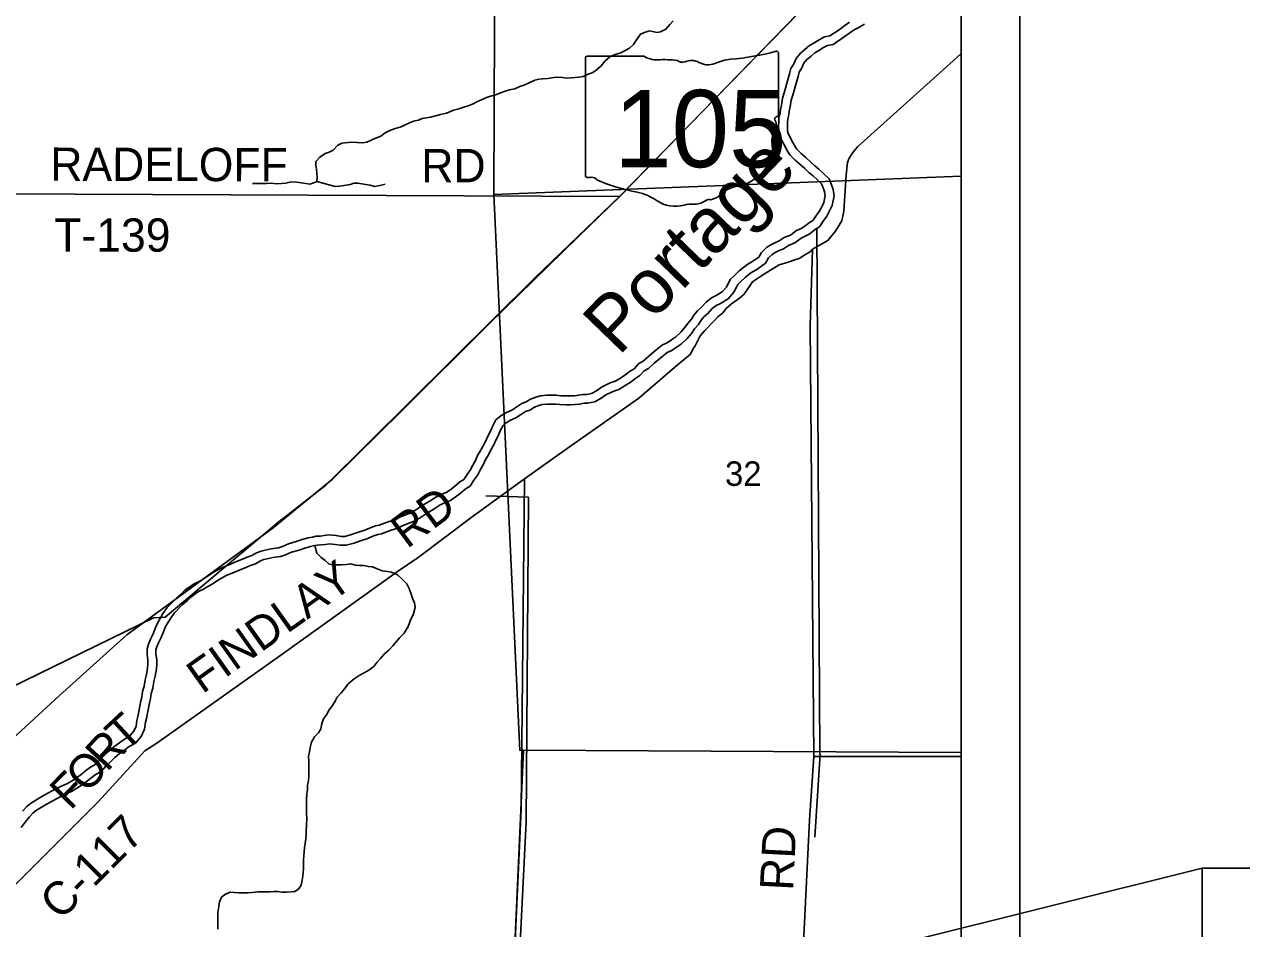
# Model space of a CAD drawing. Extents: x 0 to 34, y 0 to 22.
# Drawn here: x 7.301 to 9.379, y 18.196 to 19.739 of the extents above; entities that cross this region are included whole.
import ezdxf

# ---------------------------------------------------------------- set-up
doc = ezdxf.new("R2010")
doc.units = 0
for name, color, linetype in [('Default', 7, 'Continuous'), ('GM_X_County_Road', 7, 'Continuous'), ('GM_X_County_Road_Text', 7, 'Continuous'), ('GM_X_Major_River', 7, 'Continuous'), ('GM_X_Major_River_Text', 7, 'Continuous'), ('GM_X_Minor_River', 7, 'Continuous'), ('GM_X_Rail_Line', 7, 'Continuous'), ('GM_X_Section_Text', 7, 'Continuous'), ('GM_X_State_Location', 7, 'Continuous'), ('GM_X_State_Route', 7, 'Continuous'), ('GM_X_State_Shield', 7, 'Continuous'), ('GM_X_Township_Road', 7, 'Continuous'), ('GM_X_Township_Road_Text', 7, 'Continuous'), ('SH_Cut_Line', 7, 'Continuous'), ('SH_Data', 7, 'Continuous'), ('SH_Text', 7, 'Continuous')]:
    doc.layers.add(name, color=color, linetype=linetype)

msp = doc.modelspace()

# ---------------------------------------------------------------- linework, layer by layer
at = {"layer": 'Default'}
msp.add_lwpolyline([(8.9, 16.9874), (8.9, 20.9)], dxfattribs=at)
for points in [[(8.9, 19.4792), (8.9, 20.4788), (8.1063, 20.4559), (8.1023, 19.4482)], [(8.9, 18.4963), (8.9, 19.4792), (8.1023, 19.4482), (8.1467, 18.4995), (8.1531, 18.4998)], [(8.9, 17.4952), (8.9, 18.4963), (8.1531, 18.4998), (8.1087, 17.5031)]]:
    msp.add_lwpolyline(points, close=True, dxfattribs=at)
at = {"layer": 'GM_X_County_Road'}
msp.add_lwpolyline([(7.2847, 18.2696), (7.4268, 18.4117), (7.5065, 18.4991), (7.527, 18.5121), (7.7389, 18.6622), (7.9397, 18.8059), (7.9731, 18.8287), (8.065, 18.8983), (8.1546, 18.9633), (8.2275, 19.0149), (8.3497, 19.1008), (8.4112, 19.1537), (8.4378, 19.1757), (8.442, 19.1841), (8.4458, 19.1901), (8.4504, 19.1993), (8.4545, 19.2069), (8.4621, 19.2164), (8.4777, 19.2319), (8.4845, 19.2395), (8.4929, 19.246), (8.4986, 19.2536), (8.5077, 19.2616), (8.5218, 19.2715), (8.5297, 19.2779), (8.5438, 19.2992), (8.5624, 19.3118), (8.5893, 19.3281), (8.6045, 19.3327), (8.6159, 19.3368), (8.6231, 19.3391), (8.633, 19.3452), (8.6421, 19.3502), (8.6463, 19.3547), (8.6725, 19.3695), (8.6854, 19.3855), (8.696, 19.403), (8.6995, 19.4197), (8.7037, 19.482), (8.706, 19.5029), (8.7086, 19.5101), (8.7151, 19.5196), (8.7174, 19.5226), (8.7231, 19.5295), (8.8864, 19.6764), (8.9, 19.6888)], dxfattribs=at)
at = {"layer": 'GM_X_Major_River'}
for points in [[(8.7092, 19.742), (8.7013, 19.7366), (8.6915, 19.7294), (8.6756, 19.7187), (8.6665, 19.7171), (8.6574, 19.7121), (8.6475, 19.706), (8.6411, 19.7022), (8.6339, 19.696), (8.6256, 19.6892), (8.6184, 19.6804), (8.6143, 19.6713), (8.6094, 19.6633), (8.6067, 19.6538), (8.6026, 19.6382), (8.6, 19.6298), (8.5978, 19.6215), (8.5951, 19.6123), (8.5933, 19.6006), (8.5914, 19.5933), (8.5907, 19.5869), (8.5888, 19.5793), (8.5885, 19.5721), (8.5881, 19.5656), (8.5885, 19.5569), (8.5893, 19.5497), (8.597, 19.5338), (8.6035, 19.522)], [(8.6169, 19.5292), (8.6104, 19.5407), (8.6041, 19.5539), (8.6036, 19.5581), (8.6033, 19.5655), (8.6036, 19.5713), (8.6039, 19.5771), (8.6056, 19.5842), (8.6064, 19.5906), (8.6082, 19.5975), (8.61, 19.609), (8.6124, 19.6174), (8.6146, 19.6256), (8.6172, 19.634), (8.6214, 19.6498), (8.6234, 19.6572), (8.6277, 19.6641), (8.6314, 19.6723), (8.6364, 19.6784), (8.6436, 19.6844), (8.6499, 19.6898), (8.6554, 19.693), (8.665, 19.699), (8.6715, 19.7026), (8.6813, 19.7043), (8.7002, 19.717), (8.71, 19.7242), (8.7171, 19.729), (8.7231, 19.7322), (8.7349, 19.7391)], [(8.6035, 19.522), (8.6077, 19.5156), (8.6168, 19.5069), (8.6248, 19.5001), (8.6328, 19.4926), (8.6404, 19.4854), (8.6473, 19.4801), (8.6553, 19.4726), (8.6617, 19.4665), (8.6644, 19.4593), (8.6667, 19.4529), (8.6679, 19.4465), (8.6653, 19.4343), (8.6619, 19.4274), (8.6577, 19.4194), (8.6517, 19.4114), (8.6472, 19.4042), (8.6407, 19.4), (8.6332, 19.3939), (8.6267, 19.3904), (8.6188, 19.3866), (8.6086, 19.379), (8.5979, 19.3747), (8.5892, 19.369), (8.5817, 19.3655), (8.5752, 19.3625), (8.5677, 19.3575), (8.559, 19.3495), (8.5544, 19.3415), (8.5427, 19.3331), (8.5359, 19.3292), (8.5287, 19.3243), (8.5211, 19.3181), (8.5128, 19.3101), (8.5064, 19.304), (8.503, 19.2972), (8.4992, 19.2903), (8.492, 19.2819), (8.4818, 19.2758), (8.4739, 19.272), (8.4644, 19.2647), (8.4569, 19.2559), (8.4497, 19.2498), (8.4436, 19.2422), (8.4395, 19.2353), (8.4331, 19.2281), (8.4278, 19.2205), (8.4214, 19.2132), (8.4123, 19.2048), (8.4055, 19.2002), (8.3983, 19.1953), (8.3903, 19.1914), (8.3816, 19.1849), (8.3752, 19.1796), (8.3661, 19.1719), (8.3574, 19.1639), (8.3495, 19.1597), (8.3415, 19.1509), (8.334, 19.146), (8.3275, 19.141), (8.3165, 19.1337), (8.3094, 19.1295), (8.301, 19.1268), (8.2942, 19.1234), (8.2859, 19.1195), (8.2775, 19.1134), (8.2692, 19.1088), (8.2609, 19.1072), (8.2544, 19.1072), (8.2468, 19.1056), (8.24, 19.1049), (8.2324, 19.1044), (8.226, 19.1044), (8.2165, 19.1047), (8.2089, 19.1058), (8.1926, 19.1057), (8.182, 19.1049), (8.1755, 19.103), (8.1649, 19.0988), (8.1573, 19.0942), (8.1498, 19.0915), (8.1414, 19.0861), (8.1327, 19.0804), (8.124, 19.0765), (8.1145, 19.0712), (8.1058, 19.0635), (8.0998, 19.0525), (8.0961, 19.043), (8.0912, 19.0346), (8.0885, 19.0278), (8.0832, 19.0182), (8.0791, 19.0102), (8.0746, 19.003), (8.0712, 18.9946), (8.0663, 18.9863), (8.0618, 18.9779), (8.0554, 18.9687), (8.0512, 18.9619), (8.0444, 18.9581), (8.0349, 18.9497), (8.0274, 18.9439)], [(8.0365, 18.9318), (8.0446, 18.9379), (8.0532, 18.9456), (8.0621, 18.9506), (8.0681, 18.9605), (8.0747, 18.9699), (8.0795, 18.9788), (8.0848, 18.9879), (8.0881, 18.9961), (8.0923, 19.0027), (8.0966, 19.0111), (8.1023, 19.0213), (8.1049, 19.028), (8.1097, 19.0363), (8.1136, 19.046), (8.1179, 19.0539), (8.1234, 19.0587), (8.1308, 19.063), (8.14, 19.067), (8.1497, 19.0734), (8.1565, 19.0778), (8.1639, 19.0804), (8.1717, 19.0851), (8.1805, 19.0887), (8.1847, 19.0899), (8.1932, 19.0906), (8.2078, 19.0907), (8.2151, 19.0896), (8.2257, 19.0892), (8.2329, 19.0893), (8.2413, 19.0897), (8.2492, 19.0907), (8.256, 19.0921), (8.2623, 19.0921), (8.2744, 19.0944), (8.2857, 19.1006), (8.2936, 19.1064), (8.3008, 19.1097), (8.3068, 19.1128), (8.3156, 19.1156), (8.3246, 19.1209), (8.3364, 19.1287), (8.3428, 19.1336), (8.3515, 19.1393), (8.3589, 19.1476), (8.3662, 19.1515), (8.3761, 19.1606), (8.3849, 19.168), (8.391, 19.173), (8.3982, 19.1784), (8.4059, 19.1821), (8.414, 19.1877), (8.4217, 19.1929), (8.4322, 19.2026), (8.4397, 19.2111), (8.445, 19.2187), (8.4517, 19.2263), (8.4561, 19.2335), (8.4606, 19.2392), (8.4676, 19.2451), (8.4749, 19.2536), (8.4819, 19.259), (8.489, 19.2624), (8.502, 19.2702), (8.5118, 19.2816), (8.5164, 19.2902), (8.5188, 19.2949), (8.5233, 19.2992), (8.5312, 19.3068), (8.5378, 19.3121), (8.5439, 19.3164), (8.5509, 19.3203), (8.566, 19.3311), (8.571, 19.3399), (8.577, 19.3455), (8.5827, 19.3492), (8.5881, 19.3518), (8.5966, 19.3557), (8.605, 19.3612), (8.616, 19.3656), (8.6267, 19.3736), (8.6336, 19.3769), (8.6416, 19.3812), (8.6497, 19.3877), (8.6582, 19.3933), (8.6642, 19.4028), (8.6706, 19.4113), (8.6754, 19.4206), (8.6797, 19.4293), (8.6833, 19.4462), (8.6814, 19.4568), (8.6786, 19.4645), (8.6747, 19.4752), (8.6656, 19.4836), (8.6571, 19.4917), (8.6502, 19.497), (8.6432, 19.5036), (8.6349, 19.5114), (8.6269, 19.5182), (8.6194, 19.5254), (8.6169, 19.5292)], [(7.2953, 18.3682), (7.3026, 18.3772), (7.3095, 18.3863), (7.3155, 18.3927), (7.3202, 18.3967), (7.3284, 18.4015), (7.3371, 18.4068), (7.3472, 18.4127), (7.3579, 18.4183), (7.3671, 18.4231), (7.3731, 18.426), (7.3817, 18.4297), (7.3903, 18.435), (7.3994, 18.4408), (7.4064, 18.4462), (7.4145, 18.4525), (7.4221, 18.4581), (7.4324, 18.4642), (7.4401, 18.4725), (7.4474, 18.4798), (7.4552, 18.4873), (7.4628, 18.4936), (7.4722, 18.5006), (7.4797, 18.5061), (7.4904, 18.5119), (7.5002, 18.5235), (7.5063, 18.5357), (7.508, 18.5478), (7.5094, 18.5542), (7.5113, 18.5631), (7.5146, 18.5808), (7.5162, 18.5875), (7.5176, 18.5966), (7.5202, 18.6057), (7.5221, 18.617), (7.5243, 18.6261), (7.5264, 18.639), (7.5269, 18.647), (7.5268, 18.6548), (7.5256, 18.6647), (7.5256, 18.6711), (7.5271, 18.6763), (7.5299, 18.6834), (7.5344, 18.6924), (7.5384, 18.7021), (7.5421, 18.7113), (7.5456, 18.7171), (7.5503, 18.7248), (7.5565, 18.734), (7.5711, 18.7488), (7.5789, 18.755), (7.5849, 18.7614), (7.594, 18.7677), (7.5993, 18.7712), (7.6069, 18.7746), (7.614, 18.7793), (7.6213, 18.7835), (7.6304, 18.7897), (7.6372, 18.7938), (7.6467, 18.7986), (7.6587, 18.8034), (7.6691, 18.8077), (7.6789, 18.8119), (7.6867, 18.8152), (7.6956, 18.8182), (7.7038, 18.8229), (7.7098, 18.8252), (7.7151, 18.8265), (7.7249, 18.8287), (7.7384, 18.8304), (7.7468, 18.8334), (7.757, 18.8378), (7.7698, 18.8416), (7.7794, 18.8449), (7.7891, 18.8474), (7.7962, 18.849), (7.8011, 18.8501), (7.8074, 18.8502), (7.8149, 18.8511), (7.8213, 18.852), (7.8314, 18.8512), (7.84, 18.8496), (7.8503, 18.8496), (7.8641, 18.8534), (7.8744, 18.857), (7.8873, 18.8614), (7.8959, 18.865), (7.9043, 18.8682), (7.9106, 18.8694), (7.9253, 18.8748), (7.9344, 18.878), (7.9475, 18.8835), (7.9571, 18.8873), (7.9662, 18.8908), (7.9755, 18.8962), (7.9907, 18.9061), (7.9996, 18.9114), (8.0108, 18.9184), (8.02, 18.9229), (8.0281, 18.9263), (8.0365, 18.9318)], [(8.0274, 18.9439), (8.0209, 18.9397), (8.0137, 18.9366), (8.0035, 18.9317), (7.9918, 18.9244), (7.9827, 18.919), (7.9675, 18.9091), (7.9596, 18.9045), (7.9516, 18.9014), (7.9418, 18.8975), (7.9289, 18.8922), (7.9202, 18.8891), (7.9066, 18.8841), (7.9001, 18.8829), (7.8903, 18.8791), (7.8819, 18.8756), (7.8694, 18.8714), (7.8596, 18.8679), (7.8482, 18.8648), (7.8414, 18.8648), (7.8334, 18.8662), (7.8209, 18.8673), (7.8129, 18.8661), (7.8064, 18.8653), (7.7992, 18.8653), (7.7928, 18.8637), (7.7856, 18.8622), (7.775, 18.8595), (7.7651, 18.856), (7.7519, 18.8521), (7.7413, 18.8475), (7.7348, 18.8452), (7.7223, 18.8436), (7.7117, 18.8413), (7.7052, 18.8397), (7.6973, 18.8367), (7.6893, 18.8321), (7.6814, 18.8294), (7.673, 18.8259), (7.6632, 18.8217), (7.653, 18.8175), (7.6405, 18.8125), (7.6298, 18.8071), (7.6223, 18.8025), (7.6132, 18.7964), (7.606, 18.7921), (7.5996, 18.7879), (7.592, 18.7845), (7.5856, 18.7803), (7.575, 18.773), (7.5685, 18.7661), (7.561, 18.76), (7.5447, 18.7436), (7.5375, 18.733), (7.5326, 18.725), (7.5285, 18.7181), (7.5244, 18.7078), (7.5206, 18.6987), (7.5161, 18.6896), (7.5127, 18.6812), (7.5105, 18.6732), (7.5105, 18.6637), (7.5117, 18.6539), (7.5117, 18.6474), (7.5113, 18.6406), (7.5095, 18.6292), (7.5072, 18.62), (7.5054, 18.609), (7.5028, 18.5999), (7.5013, 18.5904), (7.4998, 18.584), (7.4964, 18.5661), (7.4946, 18.5574), (7.4931, 18.5505), (7.4916, 18.5403), (7.4875, 18.5319), (7.4807, 18.5239), (7.4716, 18.5189), (7.4633, 18.5128), (7.4534, 18.5055), (7.4451, 18.4986), (7.4368, 18.4906), (7.4292, 18.483), (7.4228, 18.4761), (7.4137, 18.4708), (7.4054, 18.4646), (7.3971, 18.4581), (7.3906, 18.4532), (7.3823, 18.4478), (7.3747, 18.4432), (7.3668, 18.4398), (7.3603, 18.4367), (7.3509, 18.4317), (7.3399, 18.426), (7.3293, 18.4198), (7.3206, 18.4145), (7.3115, 18.4091), (7.3051, 18.4037), (7.2979, 18.3961)]]:
    msp.add_lwpolyline(points, dxfattribs=at)
at = {"layer": 'GM_X_Minor_River'}
for p, q in [((8.6537, 19.3904), (8.6588, 18.4937)), ((8.0887, 18.934), (8.1617, 18.9319)), ((8.1617, 18.9319), (8.1576, 18.3773)), ((8.6591, 18.4934), (8.6502, 18.3516)), ((8.6588, 18.4937), (8.6591, 18.4934)), ((8.1576, 18.3777), (8.1136, 17.5233))]:
    msp.add_line(p, q, dxfattribs=at)
for points in [[(8.4083, 19.7446), (8.4027, 19.7381), (8.3959, 19.7301), (8.3868, 19.7259), (8.3803, 19.7247), (8.3686, 19.7273), (8.3606, 19.7253), (8.3523, 19.7215), (8.3458, 19.712), (8.3406, 19.7044), (8.3338, 19.6979), (8.319, 19.6898), (8.3091, 19.6871), (8.3, 19.6829), (8.2917, 19.6756), (8.2857, 19.668), (8.2762, 19.6596), (8.2698, 19.6558), (8.2633, 19.6535), (8.255, 19.6496), (8.2474, 19.6485), (8.2345, 19.6472), (8.2266, 19.6468), (8.2197, 19.6479), (8.2125, 19.6483), (8.2046, 19.6479), (8.1943, 19.6463), (8.186, 19.6455), (8.1791, 19.6447), (8.1723, 19.6431), (8.1636, 19.6393), (8.1553, 19.6354), (8.1469, 19.6324), (8.1382, 19.6285), (8.1291, 19.627), (8.1215, 19.6243), (8.1151, 19.6223), (8.1052, 19.6185), (8.0965, 19.6158), (8.0897, 19.6135), (8.081, 19.6096), (8.0746, 19.6069), (8.0658, 19.6023), (8.0586, 19.5996), (8.0511, 19.5973), (8.0427, 19.5942), (8.0336, 19.5923), (8.0215, 19.5869), (8.0113, 19.5846), (8.0048, 19.583), (7.9942, 19.5803), (7.9798, 19.5776), (7.9734, 19.5753), (7.965, 19.5733), (7.9582, 19.5706), (7.9487, 19.5657), (7.9423, 19.5633), (7.934, 19.561)], [(7.934, 19.561), (7.9245, 19.5572), (7.9169, 19.5533), (7.9093, 19.548), (7.9018, 19.5449), (7.8938, 19.5415), (7.8855, 19.5376), (7.8783, 19.5361), (7.86, 19.5375), (7.8536, 19.5371), (7.843, 19.5355), (7.8362, 19.5324), (7.8278, 19.5236), (7.821, 19.5202), (7.8146, 19.5179), (7.8051, 19.5118), (7.7983, 19.5045), (7.7983, 19.4981), (7.7995, 19.4912), (7.8003, 19.4848), (7.8007, 19.4776), (7.8004, 19.4704)], [(7.8005, 19.4703), (7.7882, 19.4657), (7.7738, 19.4679), (7.7616, 19.4698), (7.7544, 19.4694), (7.7465, 19.4678), (7.74, 19.467), (7.7305, 19.4666), (7.7226, 19.4673), (7.7142, 19.4672), (7.7074, 19.4668), (7.6903, 19.4667)], [(7.9169, 19.466), (7.9078, 19.4633), (7.8983, 19.4621), (7.8911, 19.464), (7.8839, 19.4651), (7.8702, 19.4673), (7.8634, 19.4673), (7.8569, 19.465), (7.8467, 19.4638), (7.8383, 19.4622), (7.8315, 19.4618), (7.8004, 19.4704)], [(7.797, 18.8491), (7.8001, 18.8361), (7.8073, 18.8289), (7.8146, 18.8236), (7.8214, 18.8172), (7.8286, 18.8161), (7.8419, 18.8165), (7.8507, 18.8166), (7.8575, 18.8178), (7.8662, 18.8159), (7.8727, 18.8152), (7.8803, 18.8152), (7.8882, 18.8134), (7.8951, 18.8127), (7.9034, 18.8097), (7.9118, 18.8059), (7.9205, 18.8048), (7.9277, 18.8037), (7.938, 18.7992), (7.9452, 18.7924), (7.9536, 18.7841), (7.9574, 18.7773), (7.9605, 18.7682), (7.964, 18.7576), (7.967, 18.7512), (7.9678, 18.7436), (7.9648, 18.731), (7.9607, 18.7238), (7.9558, 18.7112), (7.949, 18.6998), (7.9418, 18.6922), (7.9354, 18.6849), (7.9297, 18.6781), (7.9233, 18.6708), (7.9157, 18.6647), (7.9089, 18.6567), (7.9025, 18.6495), (7.8972, 18.6426), (7.8874, 18.6357), (7.8787, 18.6311), (7.8722, 18.6277), (7.8639, 18.6219), (7.8533, 18.6124), (7.8477, 18.6055), (7.8416, 18.5979), (7.8348, 18.5906), (7.8314, 18.5834), (7.8269, 18.5762), (7.8212, 18.5689), (7.8167, 18.5602), (7.8118, 18.5533), (7.8088, 18.5457), (7.8069, 18.5366), (7.8032, 18.5297), (7.796, 18.5229), (7.7911, 18.5137), (7.7885, 18.5046), (7.7874, 18.4974), (7.7859, 18.4894), (7.7863, 18.4811), (7.7867, 18.4739), (7.7863, 18.467), (7.7864, 18.4553), (7.786, 18.4484), (7.7845, 18.4401), (7.7842, 18.4321), (7.7831, 18.4253), (7.7824, 18.415), (7.7825, 18.3907), (7.7829, 18.3839), (7.7825, 18.3713), (7.7822, 18.3626), (7.7818, 18.3562), (7.7811, 18.3486), (7.7804, 18.3406), (7.7793, 18.3341), (7.7785, 18.3265), (7.7774, 18.3132), (7.7775, 18.2984), (7.7771, 18.2916), (7.7764, 18.2848), (7.7753, 18.2783), (7.7734, 18.2696), (7.7689, 18.2627), (7.7625, 18.2589), (7.7492, 18.2577), (7.7408, 18.258), (7.7333, 18.2591), (7.7268, 18.2591), (7.72, 18.2583), (7.7135, 18.2586), (7.7063, 18.2586), (7.6995, 18.2582), (7.6896, 18.2574), (7.6817, 18.2569), (7.6672, 18.2569), (7.6521, 18.2575), (7.6445, 18.2545), (7.6377, 18.2491), (7.6339, 18.2415), (7.6328, 18.2331)], [(7.6328, 18.2331), (7.6313, 18.2233), (7.6314, 18.1944)]]:
    msp.add_lwpolyline(points, dxfattribs=at)
at = {"layer": 'GM_X_Rail_Line'}
msp.add_lwpolyline([(7.1295, 18.535), (7.5214, 18.7256), (7.5415, 18.727), (7.7361, 18.8905), (7.8156, 18.9525), (8.1721, 19.3059), (8.3177, 19.4462), (8.6699, 19.8071), (8.8197, 19.9527), (8.8503, 19.9748), (8.9, 19.9949)], dxfattribs=at)
at = {"layer": 'GM_X_State_Route'}
msp.add_lwpolyline([(7.1275, 18.3685), (7.1654, 18.4136), (7.3608, 18.5932), (7.4758, 18.6969), (7.6618, 18.8326), (7.7258, 18.8796), (7.8269, 18.9622), (7.9458, 19.0794), (8.0941, 19.2274), (8.2454, 19.3754), (8.3174, 19.4447), (8.6611, 19.7985), (8.7135, 19.8476), (8.8036, 19.9332), (8.8247, 19.9539), (8.842, 19.9695), (8.8812, 19.988), (8.9, 19.9963)], dxfattribs=at)
at = {"layer": 'GM_X_State_Shield'}
for p, q in [((8.2585, 19.6808), (8.2585, 19.4807)), ((8.3582, 19.6843), (8.2617, 19.6843)), ((8.588, 19.5846), (8.588, 19.6892)), ((8.588, 19.5846), (8.588, 19.5846))]:
    msp.add_line(p, q, dxfattribs=at)
for centre, major_axis, start_param, end_param in [((8.2622, 19.6813), (0.00382, 0), 1.712693, 3.28349), ((8.3812, 19.7075), (0.037, 0), 4.042523, 4.731795), ((8.3935, 19.5719), (0.133, 0), 1.404758, 1.657858), ((8.4237, 19.6823), (0.0107, 0), 3.836095, 5.185415), ((8.4394, 19.6592), (0.0222, 0), 0.950623, 2.079405), ((8.5152, 19.6232), (0.0703, 0), 1.699011, 2.107814), ((8.4706, 19.9571), (0.3495, 0), 4.814394, 5.042369), ((8.5844, 19.6897), (0.00367, 0), 6.141152, 7.989035), ((8.468, 19.6909), (0.0267, 0), 4.081561, 5.145723), ((8.5872, 19.5769), (0.00568, 0), 1.883978, 3.671073), ((8.5511, 19.5636), (0.0341, 0), 5.934695, 6.695948), ((8.5841, 19.5841), (0.00393, 0), 5.05454, 6.418171), ((8.6012, 19.5407), (0.0248, 0), 2.387724, 3.262537), ((8.4902, 19.5274), (0.0874, 0), 5.101752, 6.440018), ((8.2623, 19.4803), (0.00385, 0), 3.00124, 4.508301), ((8.2629, 19.5008), (0.0294, 0), 4.665946, 4.897461), ((8.2689, 19.4692), (0.0106, 0), 0.519207, 1.627899), ((8.4027, 19.649), (0.2524, 0), 4.195997, 4.488961), ((8.3274, 19.3908), (0.079, 0), 0.823519, 1.323587), ((8.4664, 19.4613), (0.0282, 0), 4.937069, 5.64225), ((8.5271, 19.4245), (0.0479, 0), 1.647645, 2.488434), ((8.4129, 19.4682), (0.0501, 0), 4.026481, 4.996735), ((8.4418, 19.399), (0.0412, 0), 1.495662, 1.94098), ((8.4455, 19.4532), (0.0267, 0), 4.691044, 5.507374), ((8.4696, 19.4338), (0.00752, 0), 1.147584, 2.315152)]:
    msp.add_ellipse(centre, major_axis=major_axis, ratio=0.8, start_param=start_param, end_param=end_param, dxfattribs=at)
at = {"layer": 'GM_X_Township_Road'}
for p, q in [((7.1495, 19.4496), (8.3174, 19.4447)), ((8.6486, 18.4894), (8.9, 18.4893))]:
    msp.add_line(p, q, dxfattribs=at)
for points in [[(8.6486, 18.4894), (8.6424, 19.2241), (8.6463, 19.3547)], [(8.1256, 17.8887), (8.1488, 18.3996), (8.1546, 18.9633)], [(8.5995, 17.493), (8.6243, 18.0427), (8.6409, 18.3804), (8.6486, 18.4894)]]:
    msp.add_lwpolyline(points, dxfattribs=at)
at = {"layer": 'SH_Cut_Line'}
msp.add_lwpolyline([(8.9, 14.1), (8.9, 20.9)], dxfattribs=at)
at = {"layer": 'SH_Data'}
for p, q in [((9, 21), (9, 14)), ((8.9, 20.9), (8.9, 14.1))]:
    msp.add_line(p, q, dxfattribs=at)
at = {"layer": 'SH_Text'}
for points in [[(9.3111, 18.299), (4.9771, 17.2181), (9.3111, 18.0801)], [(9.3111, 18.299), (11.9158, 18.299), (11.9158, 16.6684), (9.3111, 16.6684)]]:
    msp.add_lwpolyline(points, close=True, dxfattribs=at)

# ---------------------------------------------------------------- texts
at = {"layer": 'GM_X_County_Road_Text'}
for s, height, rotation, p in [('RD', 0.05682, 36.7812, (7.9541, 18.8426)), ('FINDLAY', 0.05682, 35.4665, (7.6048, 18.595)), ('T', 0.0568, 42.8964, (7.4727, 18.495)), ('R', 0.0568, 47.45, (7.442, 18.4615)), ('O', 0.0568, 47.0338, (7.4076, 18.4245)), ('F', 0.0568, 45.3662, (7.3795, 18.396)), ('C-117', 0.05682, 45, (7.3625, 18.2078))]:
    msp.add_text(s, height=height, rotation=rotation, dxfattribs=at).set_placement(p)
at = {"layer": 'GM_X_Major_River_Text'}
msp.add_text('Portage', height=0.09475, rotation=45.9727, dxfattribs=at).set_placement((8.315, 19.1711))
at = {"layer": 'GM_X_Section_Text'}
msp.add_text('32', height=0.04186, rotation=0, dxfattribs=at).set_placement((8.4969, 18.951))
at = {"layer": 'GM_X_State_Location'}
msp.add_text('105', height=0.000189, rotation=0, dxfattribs=at).set_placement((8.3527, 19.5537))
for s, p in [('s', (8.4196, 19.5675)), ('r', (8.4195, 19.5675))]:
    msp.add_text(s, height=0.000189, dxfattribs=at).set_placement(p)
at = {"layer": 'GM_X_State_Shield'}
msp.add_text('105', height=0.13184, dxfattribs=at).set_placement((8.3076, 19.4948))
at = {"layer": 'GM_X_Township_Road_Text'}
for s, rotation, p in [('RADELOFF', 359.8666, (7.3452, 19.4716)), ('RD', 0, (7.9785, 19.4691)), ('T-139', 0, (7.3519, 19.3506)), ('RD', 87.0387, (8.6129, 18.2596))]:
    msp.add_text(s, height=0.05682, rotation=rotation, dxfattribs=at).set_placement(p)

doc.saveas('drawing.dxf')
